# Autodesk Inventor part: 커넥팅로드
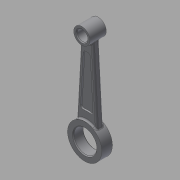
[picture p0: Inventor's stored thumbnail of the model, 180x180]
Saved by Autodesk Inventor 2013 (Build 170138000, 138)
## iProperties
Created: 2016-11
Part Number: 커넥팅로드
Material: 일반
Document SubType Name: Modeling
Designer: mduedu
Density: 1 g/cm^3
Mass: 23.9068 g
Surface Area: 114.14 cm^2
Volume: 23.9068 cm^3
Author: mduedu
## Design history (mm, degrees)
sketch "스케치1" dims "d0" = 42, "d3" = 20
  geometry: L1 (0, 0)-(0, 114); L2 (-7.5, 107.386)-(-12.5, 16.875); L3 (7.5, 107.386)-(12.5, 16.875); C1 r 14 at (0, 0); C2 r 6.5 at (0, 114); 3 further points
  constraints: 6 end point, 4 coincident, 2 centre point, 2 symmetric about line, 1 vertical, 6 other
  dimensions: "d1" = 28 diameter of C1; "d2" = 13 diameter of C2; "d4" = 114 distance of L1.start L1.end; "d6" = 12.5 distance from line of L1 L2.end; "d7" = 7.5 distance from line of L1 L2.start
extrude "돌출1" new body sketch "스케치1" stored distance "d8" = 13; taper "d9" = 0 deg
extrude "돌출2" join sketch "스케치1" stored distance "d10" = 20; taper "d11" = 0 deg
sketch "스케치2"
  geometry: L1 (-7.5, 107.386)-(-12.5, 16.875) reference; L2 (7.5, 107.386)-(12.5, 16.875) reference; A1 r 10 centre (0, 114) between (-7.5, 107.386) and (7.5, 107.386) reference; A2 r 21 centre (0, 0) between (-12.5, 16.875) and (12.5, 16.875) reference; 1 further point
extrude "돌출3" join sketch "스케치2" stored distance "d12" = 8; taper "d13" = 0 deg
sketch "스케치3"
  geometry: L1 (-7.5, 107.386)-(-12.5, 16.875) reference; L2 (7.5, 107.386)-(12.5, 16.875) reference; L3 (-4.209, 94.448)-(-7.768, 30.011); L4 (4.209, 94.448)-(7.768, 30.011); L5 (0, 94)-(0, 31); A1 r 10 centre (0, 114) between (-7.5, 107.386) and (7.5, 107.386) reference; A2 r 21 centre (0, 0) between (-12.5, 16.875) and (12.5, 16.875) reference; A3 r 20 centre (0, 114) between (-4.209, 94.448) and (4.209, 94.448); A4 r 31 centre (0, 0) between (7.768, 30.011) and (-7.768, 30.011); 1 further point
  constraints: 6 end point, 6 point on circle, 2 centre point, 2 parallel, 1 symmetric about line, 1 vertical alignment
  dimensions: "d18" = 10 radial gap between concentric circles of A3 A1; "d19" = 10 radial gap between concentric circles of A2 A4; "d20" = 4 distance between parallel lines of L3 L1
extrude "돌출4" cut sketch "스케치3" distance "d21" = 2; taper "d22" = 0 deg
fillet "모깎기1" dims "d23" = 3
fillet "모깎기2" dims "d24" = 2
fillet "모깎기3" dims "d25" = 2
chamfer "모따기1" distance "d26" = 1; stored, may be unused: second distance "d27" = 2, angle "d28" = 45 deg
node "솔리드1"
mirror "대칭1"
other parameters: "d16" = 4, "d17" = 4
